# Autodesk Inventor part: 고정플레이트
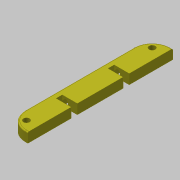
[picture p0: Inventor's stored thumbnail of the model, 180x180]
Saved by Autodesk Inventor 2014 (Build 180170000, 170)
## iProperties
Created: 2018-08
Part Number: 고정플레이트
Material: ABS 플라스틱
Document SubType Name: Modeling
Designer: mduedu
Density: 1 g/cm^3
Appearance: Canary
Author: mduedu
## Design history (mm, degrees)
sketch "스케치1"
  geometry: L1 (0, -60)-(17, -60); L2 (17, -60)-(17, 60); L3 (17, 60)-(0, 60); L4 (0, 60)-(0, -60); 2 further points
  constraints: 8 end point, 2 parallel, 1 coincident, 1 horizontal, 1 midpoint, 1 perpendicular
  dimensions: "d0" = 120 distance between parallel lines of L3 L1; "d2" = 17 distance of L1.start L1.end
extrude "돌출1" new body sketch "스케치1" distance "d3" = 8; taper "d4" = 0 deg
fillet "모깎기1" dims "d5" = 15
fillet "모깎기2" dims "d6" = 1
sketch "스케치2"
  geometry: L1 (-17, 0)-(-17, 7) reference; L2 (0, 0)-(-17, 0) reference; L3 (-12.5, 4)-(-12.5, 0); L4 (-7.5, 4)-(-7.5, 0); A1 r 2.5 centre (-10, 4) between (-12.5, 4) and (-7.5, 4)
  constraints: 4 end point, 2 perpendicular, 2 point on circle, 2 point on line, 2 tangent, 1 centre point
  dimensions: "d7" = 5 diameter of A1; "d8" = 7 distance from line of A1.centre L1; "d9" = 4 distance from line of L2 A1.centre
extrude "돌출2" cut sketch "스케치2" stored distance "d10" = 70; taper "d11" = 0 deg
fillet "모깎기3" dims "d12" = 2.5
sketch "스케치3"
  geometry: L1 (-12.5, -19)-(0, -19); L2 (0, -19)-(0, -24); L3 (0, -24)-(-12.5, -24); L4 (-12.5, -24)-(-12.5, -19); L5 (0, -59)-(0, 59) reference; L6 (-17, 45)-(-17, -45) reference; 2 further points
  constraints: 8 end point, 2 parallel, 1 horizontal, 1 midpoint, 1 perpendicular, 1 vertical alignment
  dimensions: "d13" = 4.5 distance between parallel lines of L4 L6; "d14" = 19 distance from line of L1 point (0, 0); "d15" = 5 distance of L1.end L2.end
extrude "돌출3" cut sketch "스케치3" stored distance "d16" = 70; taper "d17" = 0 deg
sketch "스케치4"
  geometry: A1 r 15 centre (-2, -45) between (-17, -45) and (-2, -60) reference; A2 r 15 centre (-2, 45) between (-2, 60) and (-17, 45) reference; A3 r 10 centre (-2, 45) between (-2, 55) and (-12, 45); A4 r 10 centre (-2, -45) between (-12, -45) and (-2, -55); 3 further points
  constraints: 6 point on circle, 2 centre point, 2 horizontal alignment, 2 vertical alignment
  dimensions: "d18" = 5 radial gap between concentric circles of A3 A2; "d19" = 5 radial gap between concentric circles of A1 A4
hole "구멍1" sketch "스케치4" at (-9.071, 52.071), (-9.071, -52.071) diameter "d20" = 5; stored, may be unused: countersink angle "d24" = 90 deg, drill point angle "d26" = 118 deg; dims "d21" = 6, "d22" = 4, "d23" = 2, "d25" = 8
node "솔리드1"
mirror "대칭1"
